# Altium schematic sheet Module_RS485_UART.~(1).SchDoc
size 420 x 297 mm; SheetNumber: 1; SheetTotal: 1
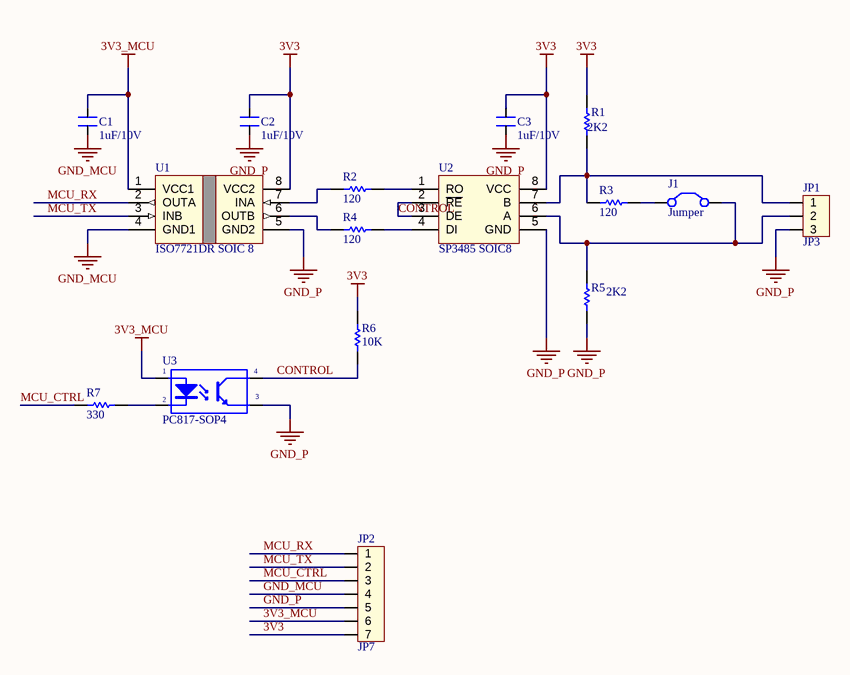
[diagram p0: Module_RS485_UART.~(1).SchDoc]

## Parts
C1  1uF/10V  [Cap Ceramic 0805 SMD]
C2  1uF/10V  [Cap Ceramic 0805 SMD]
C3  1uF/10V  [Cap Ceramic 0805 SMD]
J1  Jumper  [Header_2]
JP1  JP3  [2EDGR-5.08-03P]
JP2  JP7  [CON7]
R1  2K2  [Res 0805 SMD]
R2  120  [Res 0805 SMD]
R3  120  [Res 0805 SMD]
R4  120  [Res 0805 SMD]
R5  2K2  [Res 0805 SMD]
R6  10K  [Res 0805 SMD]
R7  330  [Res 0805 SMD]
U1  ISO7721DR SOIC 8  [ISO7721D SOIC-8 10.9mm]
U2  SP3485 SOIC8  [SP3485 SOIC-8 3.9mm]
U3  PC817-SOP4  [TPC817-4SOP]

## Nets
3V3: C2.1 C3.1 JP2.7 R1.2 R6.1 U1.8(VCC2) U2.8(VCC)
3V3_MCU: C1.1 JP2.6 U1.1(VCC1) U3.1(A)
GND_MCU: C1.2 JP2.4 U1.4(GND1)
GND_P: C2.2 C3.2 JP1.3 JP2.5 R5.1 U1.5(GND2) U2.5(GND) U3.3(E)
CONTROL: R6.2 U2.2(~{RE}) U2.3(DE) U3.4(C)
MCU_CTRL: JP2.3 R7.2
MCU_RX: JP2.1 U1.2(OUTA)
MCU_TX: JP2.2 U1.3(INB)
NetJ1_1: J1.1(C1) R3.1
NetJ1_2: J1.2(C2) JP1.2 R5.2 U2.6(A)
NetJP1_1: JP1.1 R1.1 R3.2 U2.7(B)
NetR2_1: R2.1 U2.1(RO)
NetR2_2: R2.2 U1.7(INA)
NetR4_1: R4.1 U2.4(DI)
NetR4_2: R4.2 U1.6(OUTB)
NetR7_1: R7.1 U3.2(K)

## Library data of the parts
C1-C3 = Cap Ceramic SMD
J1 = Jumper: Jumper Wire
JP1 = Con3: Connector 3
JP2 = Con7: Connector 7
R1-R7 = 249K/R0805/1%_2: RES SMD 249K OHM 1% 1/10W 0805; Manufacturer: Yageo; Manufacturer Part Number: RC0603FR-07249KL; Power (Watts): 0.1W, 1/10W; Temperature Coefficient: ±100ppm/°C
U1 = ISO7721DR SOIC 8: ISO772x High-Speed, Robust EMC, Reinforced Dual-Channel Digital Isolators
U3 = PC817: Optoisolator Transistor Output 5000Vrms 1 Channel 4-SOP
